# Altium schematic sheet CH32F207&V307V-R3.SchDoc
size A2
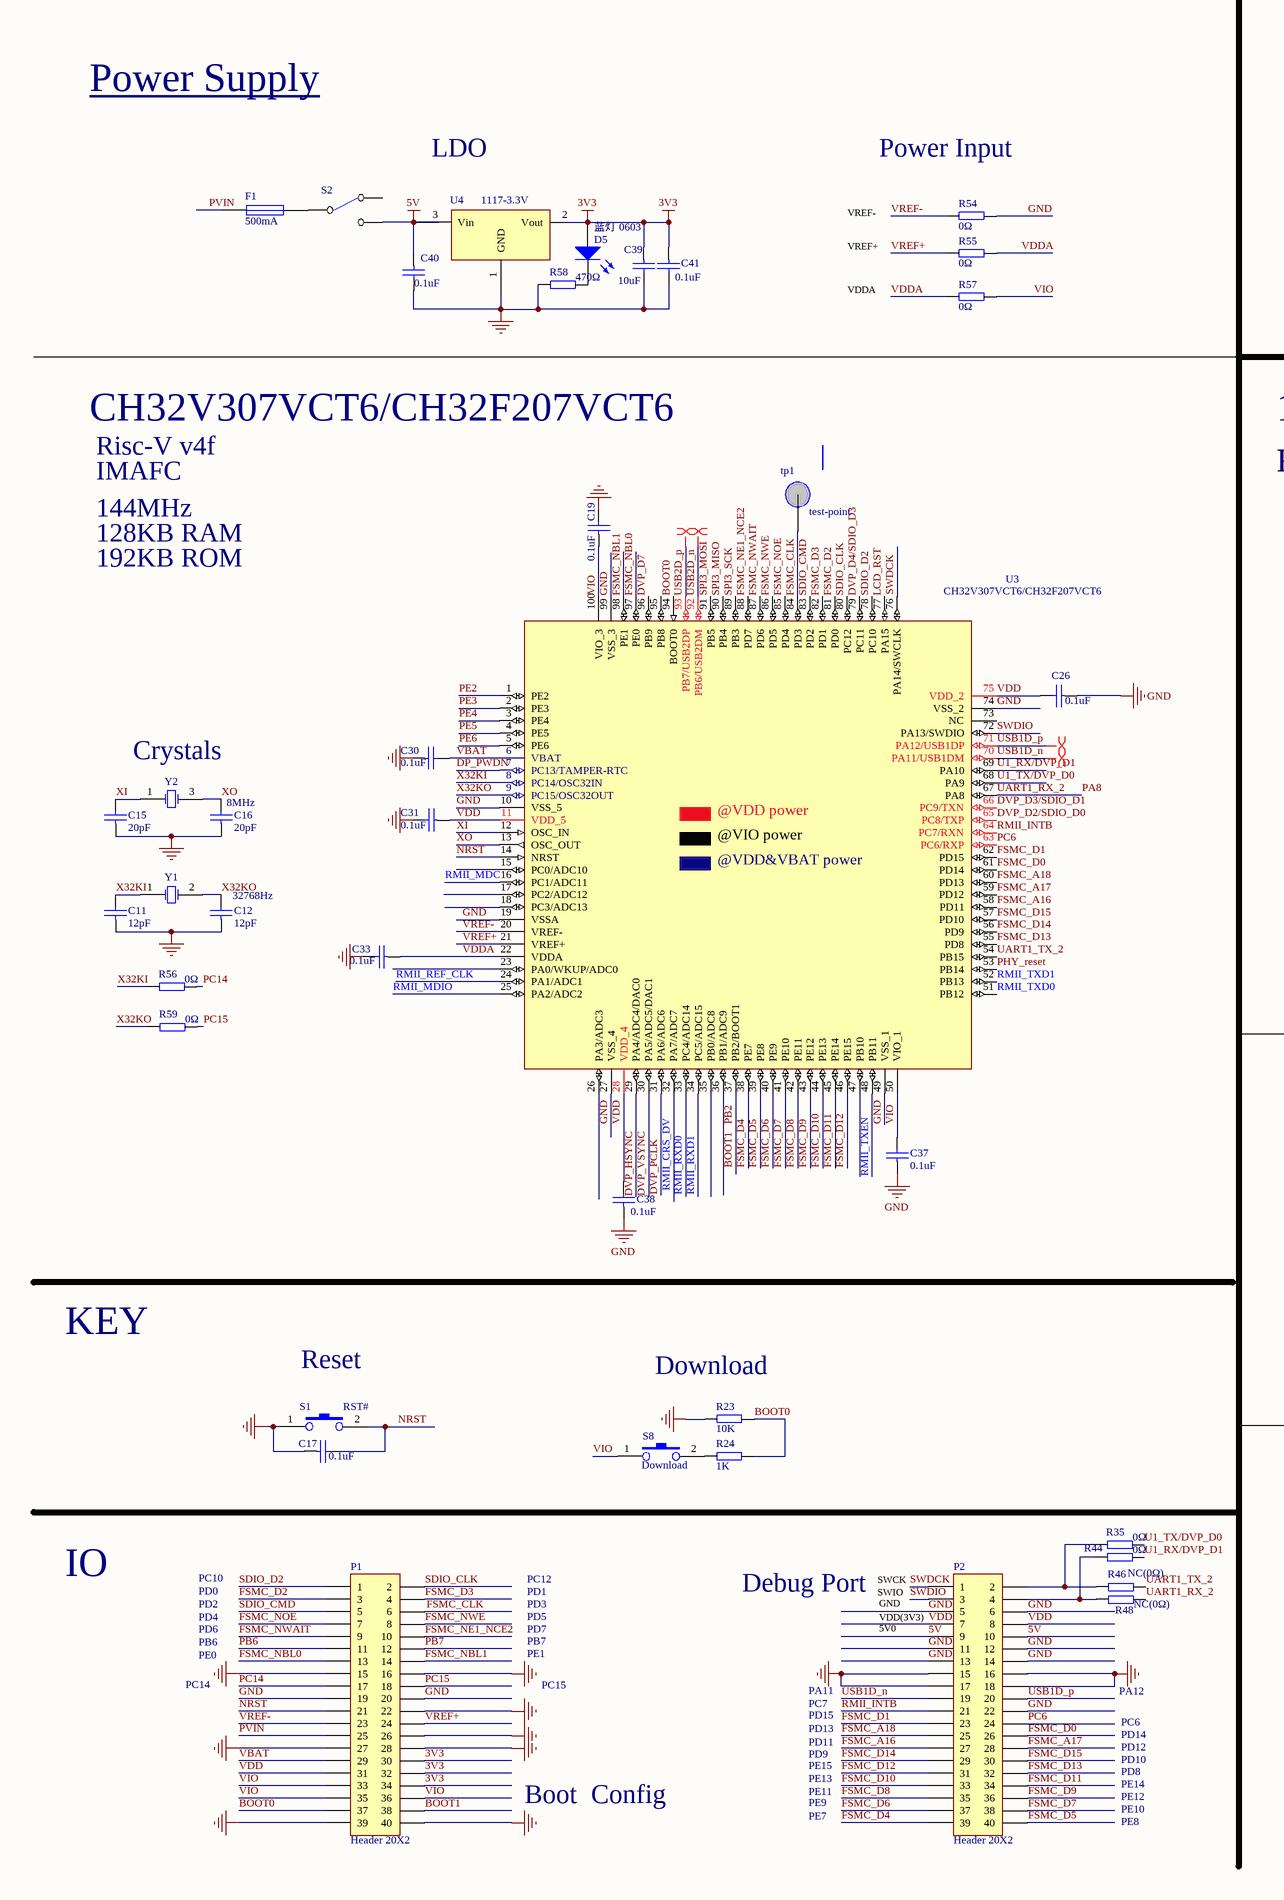
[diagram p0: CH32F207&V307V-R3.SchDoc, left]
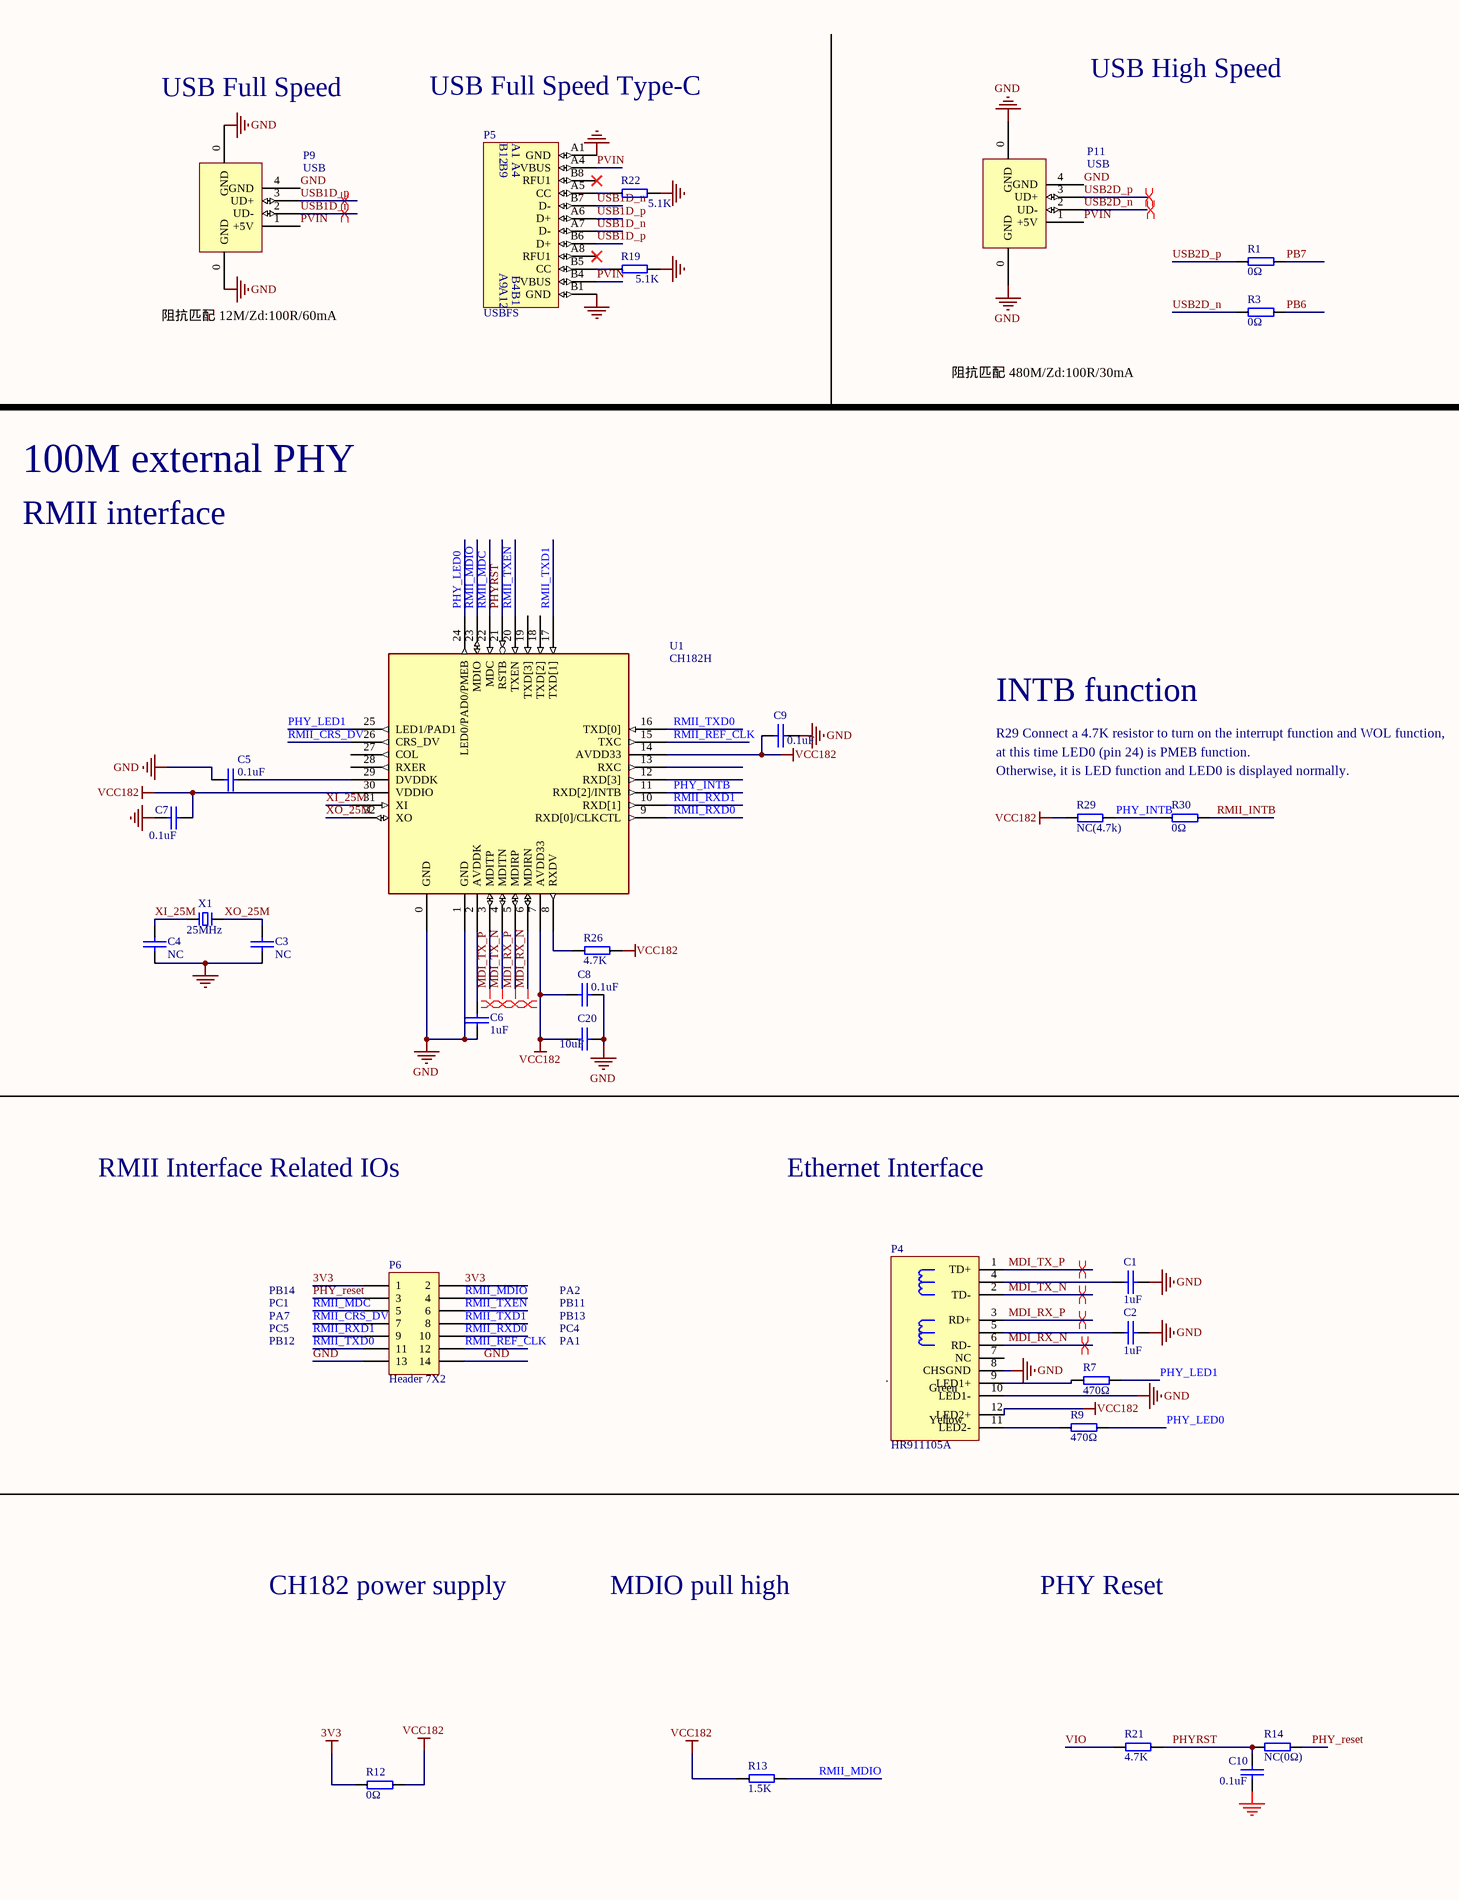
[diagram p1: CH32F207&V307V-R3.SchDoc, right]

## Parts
C1  1uF  [0603_C]
C2  1uF  [0603_C]
C3  NC  [0603_C]
C4  NC  [0603_C]
C5  0.1uF  [0603_C]
C6  1uF  [0603_C]
C7  0.1uF  [0603_C]
C8  0.1uF  [0603_C]
C9  0.1uF  [0603_C]
C10  0.1uF  [0603_C]
C11  12pF  [0603_C]
C12  12pF  [0603_C]
C15  20pF  [0603_C]
C16  20pF  [0603_C]
C17  0.1uF  [0603_C]
C19  0.1uF  [0603_C]
C20  10uF  [0603_C]
C26  0.1uF  [0603_C]
C30  0.1uF  [0603_C]
C31  0.1uF  [0603_C]
C33  0.1uF  [0603_C]
C37  0.1uF  [0603_C]
C38  0.1uF  [0603_C]
C39  10uF  [0603_C]
C40  0.1uF  [0603_C]
C41  0.1uF  [0603_C]
D5  蓝灯 0603  [0603_LED_S1]
F1  500mA  [0805]
P1  Header 20X2  [HDR2X20]
P2  Header 20X2  [HDR2X20]
P4  HR911105A  [HR911105A]
P5  USBFS  [TYPE-C-Receptacle-2.0]
P6  Header 7X2  [IDC14-2.54mm]
P9  USB  [USBAF]
P11  USB  [USBAF]
R1  0Ω  [0603]
R3  0Ω  [0603]
R7  470Ω  [0603]
R9  470Ω  [0603]
R12  0Ω  [0603]
R13  1.5K  [0603]
R14  NC(0Ω)  [0603]
R19  5.1K  [0603]
R21  4.7K  [0603]
R22  5.1K  [0603]
R23  10K  [0603]
R24  1K  [0603]
R26  4.7K  [0603]
R29  NC(4.7k)  [0603]
R30  0Ω  [0603]
R35  0Ω  [0603]
R44  0Ω  [0603]
R46  NC(0Ω)  [0603]
R48  NC(0Ω)  [0603]
R54  0Ω  [0603]
R55  0Ω  [0603]
R56  0Ω  [0603]
R57  0Ω  [0603]
R58  470Ω  [0603]
R59  0Ω  [0603]
S1  RST#  [SMD_6.1x3.65x2.5mm-KEY]
S2  SW SPDT  [Horizontal Slide Switch_8.7x4.4mm-2D]  (value not drawn)
S8  Download  [SMD_6.1x3.65x2.5mm-KEY]
tp1  test-point  [POINT]
U1  CH182H  [QFN32_5X5]
U3  CH32V307VCT6/CH32F207VCT6  [LQFP100]
U4  1117-3.3V  [SOT-223]
X1  25MHz  [SMD-3225_4P]
Y1  32768Hz  [FC-135]
Y2  8MHz  [SMD-3225_4P]

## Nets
3V3: C39.1 C41.1 D5.A P1.30 P1.32 P1.34 P6.1 P6.2 R12.2 U4.2(Vout)
5V: C40.1 P2.9 P2.10 S2.2(NC) U4.3(Vin)
GND: C1.1 C2.1 C3.1 C4.1 C5.1 C6.1 C7.1 C8.1 C9.1 C10.1 C11.1 C12.1 C15.1 C16.1 C17.1 C19.2 C20.1 C26.1 C30.1 C31.2 C33.2 C37.1 C38.1 C39.2 C40.2 C41.2 P1.15 P1.16 P1.19 P1.20 P1.22 P1.26 P1.27 P1.28 P1.39 P1.40 P2.5 P2.6 P2.11 P2.12 P2.13 P2.14 P2.15 P2.16 P2.17 P2.18 P2.22 P4.8(CHSGND) P4.10(LED1-) P5.A1(GND) P5.B1(GND) P6.13 P6.14 P9.0(GND) P9.4(GND) P11.0(GND) P11.4(GND) R19.2 R22.2 R23.2 R54.1 R58.1 S1.1 U1.0(GND) U1.1(GND) U3.10(VSS_5) U3.19(VSSA) U3.27(VSS_4) U3.49(VSS_1) U3.74(VSS_2) U3.99(VSS_3) U4.1(GND)
VCC182: C7.2 C8.2 C9.2 C20.2 P4.12(LED2+) R12.1 R13.1 R26.1 R29.2 U1.7(AVDD33) U1.14(AVDD33) U1.30(VDDIO)
BOOT0: P1.37 R23.1 R24.1 U3.94(BOOT0)
BOOT1: P1.38 U3.37(PB2/BOOT1)  [also labelled PB2]
DP_PWDN: U3.7(PC13/TAMPER-RTC)
DVP_D2/SDIO_D0: U3.65(PC8/TXP)
DVP_D3/SDIO_D1: U3.66(PC9/TXN)
DVP_D4/SDIO_D3: U3.79(PC11)
DVP_D7: U3.96(PB9)
DVP_HSYNC: U3.29(PA4/ADC4/DAC0)
DVP_PCLK: U3.31(PA6/ADC6)
DVP_VSYNC: U3.30(PA5/ADC5/DAC1)
FSMC_A16: P2.27 U3.58(PD11)
FSMC_A17: P2.28 U3.59(PD12)
FSMC_A18: P2.25 U3.60(PD13)
FSMC_CLK: P1.6 tp1.1(point) U3.84(PD3)
FSMC_D0: P2.26 U3.61(PD14)
FSMC_D1: P2.23 U3.62(PD15)
FSMC_D2: P1.3 U3.81(PD0)
FSMC_D3: P1.4 U3.82(PD1)
FSMC_D4: P2.39 U3.38(PE7)
FSMC_D5: P2.40 U3.39(PE8)
FSMC_D6: P2.37 U3.40(PE9)
FSMC_D7: P2.38 U3.41(PE10)
FSMC_D8: P2.35 U3.42(PE11)
FSMC_D9: P2.36 U3.43(PE12)
FSMC_D10: P2.33 U3.44(PE13)
FSMC_D11: P2.34 U3.45(PE14)
FSMC_D12: P2.31 U3.46(PE15)
FSMC_D13: P2.32 U3.55(PD8)
FSMC_D14: P2.29 U3.56(PD9)
FSMC_D15: P2.30 U3.57(PD10)
FSMC_NBL0: P1.13 U3.97(PE0)
FSMC_NBL1: P1.14 U3.98(PE1)
FSMC_NE1_NCE2: P1.10 U3.88(PD7)
FSMC_NOE: P1.7 U3.85(PD4)
FSMC_NWAIT: P1.9 U3.87(PD6)
FSMC_NWE: P1.8 U3.86(PD5)
LCD_RST: U3.77(PA15)
MDI_RX_N: P4.6(RD-) U1.6(MDIRN)
MDI_RX_P: P4.3(RD+) U1.5(MDIRP)
MDI_TX_N: P4.2(TD-) U1.4(MDITN)
MDI_TX_P: P4.1(TD+) U1.3(MDITP)
NRST: C17.2 P1.21 S1.2 U3.14(NRST)
PA8: R48.2 U3.67(PA8)  [also labelled UART1_RX_2]
PB6: P1.11 R3.2
PB7: P1.12 R1.2
PC6: P2.24 U3.63(PC6/RXP)
PC14: P1.17 R56.2
PC15: P1.18 R59.2
PE2: U3.1(PE2)
PE3: U3.2(PE3)
PE4: U3.3(PE4)
PE5: U3.4(PE5)
PE6: U3.5(PE6)
PHY_INTB: R29.1 R30.1 U1.11(RXD[2]/INTB)
PHY_LED0: R9.2 U1.24(LED0/PAD0/PMEB)
PHY_LED1: R7.2 U1.25(LED1/PAD1)
PHY_reset: P6.3 R14.2 U3.53(PB14)
PHYRST: C10.2 R14.1 R21.1 U1.21(RSTB)
PVIN: F1.1 P1.25 P5.A4(VBUS) P5.B4(VBUS) P9.1(+5V) P11.1(+5V)
RMII_CRS_DV: P6.7 U1.26(CRS_DV) U3.32(PA7/ADC7)
RMII_INTB: P2.21 R30.2 U3.64(PC7/RXN)
RMII_MDC: P6.5 U1.22(MDC) U3.16(PC1/ADC11)
RMII_MDIO: P6.4 R13.2 U1.23(MDIO) U3.25(PA2/ADC2)
RMII_REF_CLK: P6.12 U1.15(TXC) U3.24(PA1/ADC1)
RMII_RXD0: P6.10 U1.9(RXD[0]/CLKCTL) U3.33(PC4/ADC14)
RMII_RXD1: P6.9 U1.10(RXD[1]) U3.34(PC5/ADC15)
RMII_TXD0: P6.11 U1.16(TXD[0]) U3.51(PB12)
RMII_TXD1: P6.8 U1.17(TXD[1]) U3.52(PB13)
RMII_TXEN: P6.6 U1.20(TXEN) U3.48(PB11)
SDIO_CLK: P1.2 U3.80(PC12)
SDIO_CMD: P1.5 U3.83(PD2)
SDIO_D2: P1.1 U3.78(PC10)
SPI3_MISO: U3.90(PB4)
SPI3_MOSI: U3.91(PB5)
SPI3_SCK: U3.89(PB3)
SWDCK: P2.1 U3.76(PA14/SWCLK)
SWDIO: P2.3 U3.72(PA13/SWDIO)
U1_RX/DVP_D1: R44.2 U3.69(PA10)
U1_TX/DVP_D0: R35.2 U3.68(PA9)
UART1_TX_2: R46.2 U3.54(PB15)
USB1D_n: P2.19 P5.A7(D-) P5.B7(D-) P9.2(UD-) U3.70(PA11/USB1DM)
USB1D_p: P2.20 P5.A6(D+) P5.B6(D+) P9.3(UD+) U3.71(PA12/USB1DP)
USB2D_n: P11.2(UD-) R3.1 U3.92(PB6/USB2DM)
USB2D_p: P11.3(UD+) R1.1 U3.93(PB7/USB2DP)
VBAT: C30.2 P1.29 U3.6(VBAT)
VDD: C26.2 C31.1 C38.2 P1.31 P2.7 P2.8 U3.11(VDD_5) U3.28(VDD_4) U3.75(VDD_2)
VDDA: C33.1 R55.1 R57.2 U3.22(VDDA)
VIO: C19.1 C37.2 P1.33 P1.35 P1.36 R21.2 R57.1 S8.1 U3.50(VIO_1) U3.100(VIO_3)
VREF+: P1.24 R55.2 U3.21(VREF+)
VREF-: P1.23 R54.2 U3.20(VREF-)
X32KI: C11.2 R56.1 U3.8(PC14/OSC32IN) Y1.1(OSC1)
X32KO: C12.2 R59.1 U3.9(PC15/OSC32OUT) Y1.2(OSC2)
XI: C15.2 U3.12(OSC_IN) Y2.1(OSC1)
XI_25M: C4.2 U1.31(XI) X1.1
XO: C16.2 U3.13(OSC_OUT) Y2.3(OSC2)
XO_25M: C3.2 U1.32(XO) X1.3
NetC1_2: C1.2 P4.4
NetC2_2: C2.2 P4.5
NetC5_2: C5.2 U1.29(DVDDK)
NetC6_2: C6.2 U1.2(AVDDK)
NetD5_K: D5.K R58.2
NetF1_2: F1.2 S2.1(COMMON)
NetP2_2: P2.2 R35.1 R46.1
NetP2_4: P2.4 R44.1 R48.1
NetP4_9: P4.9(LED1+) R7.1
NetP4_11: P4.11(LED2-) R9.1
NetP5_A5: P5.A5(CC) R22.1
NetP5_B5: P5.B5(CC) R19.1
NetR24_2: R24.2 S8.2
NetR26_2: R26.2 U1.8(RXDV)

Not connected (* = marked no-connect by the designer): P4 7(NC); P5 A8(RFU1)* B8(RFU1)*; S2 3(NO); U1 12(RXD[3]) 13(RXC) 18(TXD[2]) 19(TXD[3]) 27(COL) 28(RXER); U3 15(PC0/ADC10) 17(PC2/ADC12) 18(PC3/ADC13) 23(PA0/WKUP/ADC0) 26(PA3/ADC3) 35(PB0/ADC8) 36(PB1/ADC9) 47(PB10) 73(NC) 95(PB8)

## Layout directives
differential pair: MDI_RX_N, MDI_RX_P, MDI_TX_N, MDI_TX_P, USB1D_n, USB1D_p, USB2D_n, USB2D_p

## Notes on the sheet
- USB Full Speed
- USB Full Speed Type-C
- USB High Speed
- Power Supply <Power supply>
- LDO
- Power Input
- VREF-
- VREF+
- VDDA
- 阻抗匹配 12M/Zd:100R/60mA
- 阻抗匹配 480M/Zd:100R/30mA
- CH32V307VCT6/CH32F207VCT6
- 100M external PHY
- Risc-V v4f
- IMAFC
- RMII interface
- 144MHz
- 128KB RAM
- 192KB ROM
- INTB function
- R29 Connect a 4.7K resistor to turn on the interrupt function and WOL function,
- at this time LED0 (pin 24) is PMEB function.
- Otherwise, it is LED function and LED0 is displayed normally.
- Crystals
- RMII Interface Related IOs
- Ethernet Interface
- PC1
- PB14
- PA2
- PB11
- PC5
- PB12
- PA7
- PC4
- PB13
- PA1
- KEY
- Reset
- (near R23) Download
- CH182 power supply
- MDIO pull high
- PHY Reset
- IO
- PC10
- PD2
- PD0
- PD5
- PD3
- PD1
- PC12
- Debug Port
- SWCK
- SWIO
- GND
- PD4
- PD6
- PB6
- PE0
- PE1
- PB7
- PD7
- (near P2) VDD(3V3)
- 5V0
- PC14
- PC15
- PA11
- PC7
- PD15
- PD13
- PA12
- PD14
- PC6
- Boot  Config
- PD11
- PD9
- PE15
- PE13
- PE11
- PE9
- PE12
- PE14
- PD8
- PD10
- PD12
- PE7
- PE8
- PE10

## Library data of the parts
C1-C12 C15-C17 C19 C20 C26 C30 C31 C33 C37-C41 = CAP: Capacitor
D5 = 0603 蓝灯: 发光二极管
F1 = Fuse 1: Fuse
P1 P2 = Header 20X2: Header, 20-Pin, Dual row
P4 = HR911105A_1
P5 = TYPE-C1
P6 = Header 7X2: Header, 7-Pin, Dual row
P9 P11 = USB: USB Port
R1 R3 R7 R9 R12-R14 R19 R21-R24 R26 R29 R30 R35 R44 R46 R48 R54-R59 = RES
S1 S8 = KEY1
tp1 = test-point: 测试点
U1 = CH182H: MII/RMII 10/100M Ethernet PHY (Transceiver) with auto MDIX
U3 = CH32V307V: RISC-V FPU HD-MCU, 144MHz, USB_480M, USB OTG, 1000M Ethernet MAC, 2*CAN, FSMC+DVP
X1 = XTAL-2P: 2脚无源脚晶振
Y1 Y2 = XTAL: Crystal Oscillator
